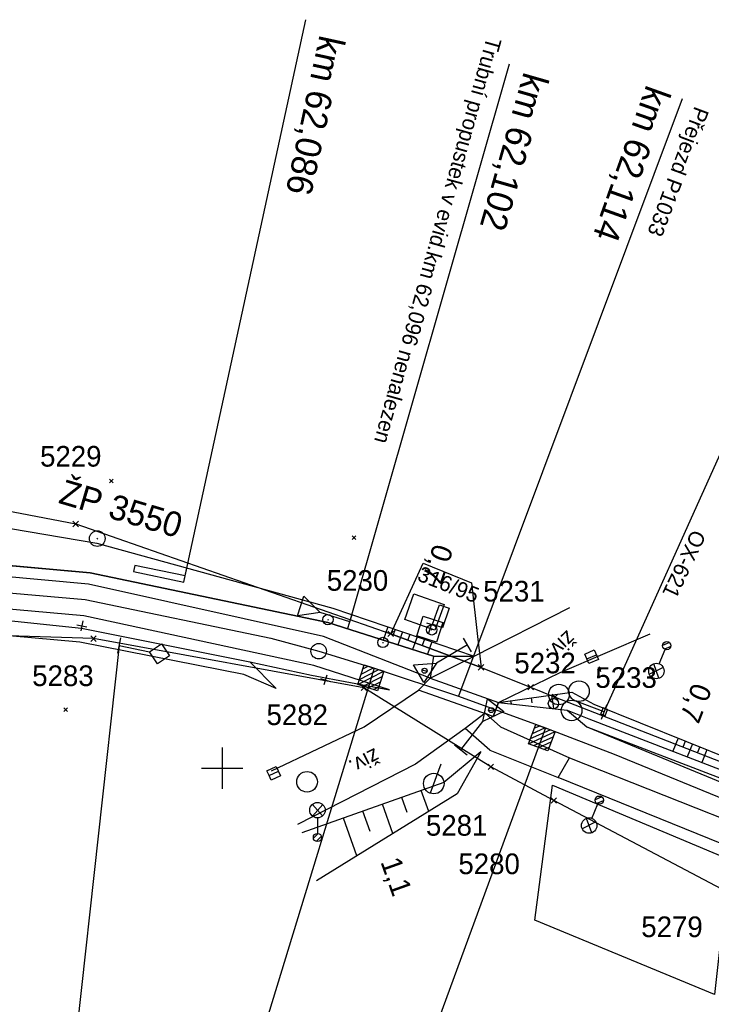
# Model space of a CAD drawing. Extents: x -805636 to -804553, y -1165340 to -1164656.
# Drawn here: x -805419.6 to -805352.6, y -1164922.9 to -1164827.5 of the extents above; entities that cross this region are included whole.
import ezdxf

# ---------------------------------------------------------------- set-up
doc = ezdxf.new("R2010")
doc.units = 0
for name, color, linetype in [('0381KM061-064P - Vrstva 1', 7, 'Continuous'), ('0381KM061-064P - Vrstva 12', 7, 'Continuous'), ('0381KM061-064P - Vrstva 16', 7, 'Continuous'), ('0381KM061-064P - Vrstva 17', 7, 'Continuous'), ('0381KM061-064P - Vrstva 19', 7, 'Continuous'), ('0381KM061-064P - Vrstva 23', 7, 'Continuous'), ('0381KM061-064P - Vrstva 25', 7, 'Continuous'), ('0381KM061-064P - Vrstva 27', 7, 'Continuous'), ('0381KM061-064P - Vrstva 3', 7, 'Continuous'), ('0381KM061-064P - Vrstva 33', 7, 'Continuous'), ('0381KM061-064P - Vrstva 4', 7, 'Continuous'), ('0381KM061-064P - Vrstva 43', 7, 'Continuous'), ('0381KM061-064P - Vrstva 48', 7, 'Continuous'), ('0381KM061-064P - Vrstva 49', 7, 'Continuous'), ('0381KM061-064P - Vrstva 51', 7, 'Continuous'), ('0381KM061-064P - Vrstva 55', 7, 'Continuous'), ('0381KM061-064P - Vrstva 57', 7, 'Continuous'), ('0381KM061-064P - Vrstva 7', 7, 'Continuous'), ('0381KM061-064P - Vrstva 8', 7, 'Continuous'), ('0381KM061-064P - Vrstva 9', 7, 'Continuous'), ('krizky_1000 - Vrstva 1', 7, 'Continuous'), ('szdc - hran DP', 7, 'Continuous'), ('szdc - szdc_cislo', 7, 'Continuous'), ('szdc - szdc_krizek', 7, 'Continuous'), ('vyt_sit - stávající', 7, 'Continuous')]:
    doc.layers.add(name, color=color, linetype=linetype)

msp = doc.modelspace()

# ---------------------------------------------------------------- linework, layer by layer
at = {"layer": '0381KM061-064P - Vrstva 1'}
msp.add_line((-805413.273, -1164883.656), (-805395.309, -1164887.389), dxfattribs=at)
for points in [[(-805621.704, -1164896.484), (-805615.585, -1164895.981), (-805590.014, -1164893.62), (-805528.478, -1164887.901), (-805486.763, -1164883.981), (-805461.299, -1164882.035), (-805437.692, -1164881.512), (-805413.273, -1164883.656)], [(-805395.309, -1164887.389), (-805390.659, -1164888.66), (-805385.303, -1164890.297), (-805377.115, -1164893.006), (-805368.704, -1164896.094), (-805362.065, -1164898.642)], [(-805362.065, -1164898.642), (-805347.387, -1164904.644), (-805344.651, -1164905.782)]]:
    msp.add_lwpolyline(points, dxfattribs=at)
at = {"layer": '0381KM061-064P - Vrstva 12'}
for p, q in [((-805363.346, -1164894.76), (-805363.111, -1164894.153)), ((-805362.921, -1164894.925), (-805362.686, -1164894.318)), ((-805362.921, -1164894.925), (-805362.686, -1164894.318))]:
    msp.add_line(p, q, dxfattribs=at)
for points in [[(-805363.346, -1164894.76), (-805363.346, -1164894.76), (-805363.111, -1164894.153), (-805363.111, -1164894.153), (-805362.686, -1164894.318), (-805362.686, -1164894.318), (-805363.111, -1164894.153)], [(-805363.346, -1164894.76), (-805362.921, -1164894.925), (-805362.921, -1164894.925), (-805363.346, -1164894.76)]]:
    msp.add_lwpolyline(points, dxfattribs=at)
at = {"layer": '0381KM061-064P - Vrstva 16'}
msp.add_lwpolyline([(-805366.38, -1164898.984), (-805348.12, -1164906.22), (-805348.611, -1164907.57), (-805349.086, -1164908.359), (-805367.461, -1164900.883), (-805366.38, -1164898.984)], dxfattribs=at)
at = {"layer": '0381KM061-064P - Vrstva 17'}
msp.add_lwpolyline([(-805369.748, -1164914.704), (-805368.039, -1164901.633), (-805350.89, -1164908.843), (-805352.324, -1164921.909), (-805369.748, -1164914.704)], dxfattribs=at)
at = {"layer": '0381KM061-064P - Vrstva 23'}
msp.add_lwpolyline([(-805382.318, -1164885.581), (-805381.437, -1164883.103), (-805378.521, -1164884.128), (-805379.402, -1164886.606)], close=True, dxfattribs=at)
at = {"layer": '0381KM061-064P - Vrstva 25'}
for p, q in [((-805356.707, -1164887.822), (-805357.359, -1164888.095)), ((-805356.572, -1164888.198), (-805357.183, -1164888.455)), ((-805357.681, -1164889.884), (-805357.113, -1164888.495)), ((-805357.305, -1164890.229), (-805358.64, -1164890.894)), ((-805357.719, -1164891.28), (-805358.218, -1164889.875)), ((-805391.275, -1164903.493), (-805390.281, -1164904.605)), ((-805391.26, -1164904.623), (-805390.276, -1164903.502)), ((-805364.199, -1164904.849), (-805363.647, -1164903.455)), ((-805363.248, -1164902.777), (-805363.897, -1164903.058)), ((-805363.108, -1164903.152), (-805363.717, -1164903.415)), ((-805390.781, -1164904.8), (-805390.781, -1164906.3)), ((-805363.819, -1164905.191), (-805365.147, -1164905.87)), ((-805364.221, -1164906.247), (-805364.735, -1164904.847)), ((-805391.17, -1164906.78), (-805390.701, -1164906.311)), ((-805390.902, -1164907.077), (-805390.402, -1164906.577))]:
    msp.add_line(p, q, dxfattribs=at)
msp.add_lwpolyline([(-805378.687, -1164886.382), (-805379.629, -1164886.047), (-805378.959, -1164884.162), (-805378.017, -1164884.497), (-805378.687, -1164886.382)], dxfattribs=at)
for centre, radius in [((-805356.962, -1164888.125), 0.4), ((-805356.962, -1164888.125), 0.4), ((-805357.962, -1164890.578), 0.749), ((-805363.499, -1164903.083), 0.4), ((-805363.499, -1164903.083), 0.4), ((-805390.784, -1164904.052), 0.749), ((-805364.472, -1164905.546), 0.749), ((-805390.781, -1164906.7), 0.4), ((-805390.781, -1164906.7), 0.4)]:
    msp.add_circle(centre, radius, dxfattribs=at)
at = {"layer": '0381KM061-064P - Vrstva 27'}
for p, q in [((-805379.668, -1164886.609), (-805379.762, -1164886.577)), ((-805384.49, -1164887.813), (-805384.39, -1164887.813)), ((-805367.983, -1164893.734), (-805367.883, -1164893.734))]:
    msp.add_line(p, q, dxfattribs=at)
for centre in [(-805379.715, -1164886.593), (-805384.44, -1164887.813), (-805367.933, -1164893.734)]:
    msp.add_circle(centre, 0.5, dxfattribs=at)
at = {"layer": '0381KM061-064P - Vrstva 3'}
for p, q in [((-805385.303, -1164890.297), (-805402.596, -1164946.877)), ((-805386.542, -1164890.886), (-805385.361, -1164890.278)), ((-805386.38, -1164890.381), (-805385.866, -1164890.116)), ((-805386.866, -1164891.896), (-805384.351, -1164890.603)), ((-805386.704, -1164891.391), (-805384.855, -1164890.441)), ((-805386.362, -1164892.058), (-805384.513, -1164891.107)), ((-805385.856, -1164892.22), (-805384.675, -1164891.613)), ((-805385.351, -1164892.382), (-805384.837, -1164892.117)), ((-805369.97, -1164896.623), (-805368.761, -1164896.073)), ((-805369.784, -1164896.126), (-805369.257, -1164895.887)), ((-805368.704, -1164896.094), (-805389.1, -1164951.648)), ((-805370.342, -1164897.616), (-805367.768, -1164896.445)), ((-805370.156, -1164897.12), (-805368.264, -1164896.259)), ((-805369.846, -1164897.802), (-805367.953, -1164896.941)), ((-805369.348, -1164897.988), (-805368.14, -1164897.438)), ((-805368.852, -1164898.174), (-805368.325, -1164897.935))]:
    msp.add_line(p, q, dxfattribs=at)
for points in [[(-805386.255, -1164889.991), (-805384.351, -1164890.603), (-805384.962, -1164892.507), (-805386.866, -1164891.896)], [(-805369.64, -1164895.743), (-805367.768, -1164896.445), (-805368.469, -1164898.318), (-805370.342, -1164897.616)]]:
    msp.add_lwpolyline(points, close=True, dxfattribs=at)
at = {"layer": '0381KM061-064P - Vrstva 33'}
for p, q in [((-805380.216, -1164885.895), (-805379.266, -1164886.209)), ((-805379.741, -1164886.052), (-805380.055, -1164887.002))]:
    msp.add_line(p, q, dxfattribs=at)
msp.add_lwpolyline([(-805380.533, -1164885.264), (-805378.635, -1164885.892), (-805379.263, -1164887.79), (-805381.161, -1164887.162), (-805380.533, -1164885.264)], dxfattribs=at)
at = {"layer": '0381KM061-064P - Vrstva 4'}
for p, q in [((-805355.471, -1164835.15), (-805377.115, -1164893.006)), ((-805437.823, -1164878.806), (-805412.781, -1164881.052)), ((-805412.96, -1164882.157), (-805437.678, -1164879.902)), ((-805412.781, -1164881.052), (-805389.788, -1164885.886)), ((-805390.184, -1164887.249), (-805412.96, -1164882.157)), ((-805379.867, -1164891.266), (-805390.184, -1164887.249)), ((-805375.866, -1164888.727), (-805376.654, -1164887.385)), ((-805380.174, -1164890.612), (-805380.647, -1164890.487)), ((-805374.205, -1164894.39), (-805373.719, -1164894.33)), ((-805377.504, -1164897.741), (-805376.274, -1164898.693))]:
    msp.add_line(p, q, dxfattribs=at)
for points in [[(-805383.815, -1164892.413), (-805391.138, -1164890.05), (-805413.398, -1164885.24), (-805437.693, -1164883.083), (-805461.239, -1164883.617), (-805489.811, -1164885.789), (-805528.465, -1164889.37), (-805589.939, -1164894.996), (-805615.477, -1164897.548), (-805622.384, -1164898.082)], [(-805622.831, -1164899.132), (-805615.585, -1164898.49), (-805589.92, -1164896.02), (-805528.493, -1164890.341), (-805490.028, -1164887.057), (-805461.175, -1164884.746), (-805437.909, -1164883.87), (-805413.614, -1164886.429), (-805397.335, -1164889.692), (-805391.357, -1164890.969), (-805383.815, -1164892.413)], [(-805389.788, -1164885.886), (-805379.556, -1164889.142), (-805379.867, -1164891.266)], [(-805376.26, -1164888.056), (-805379.252, -1164889.828), (-805380.475, -1164891.699), (-805381.498, -1164889.982), (-805379.252, -1164889.828)], [(-805380.989, -1164892.419), (-805379.867, -1164891.266), (-805373.247, -1164893.625), (-805373.771, -1164894.981), (-805380.989, -1164892.419)], [(-805376.889, -1164898.217), (-805374.77, -1164895.461), (-805374.329, -1164893.269), (-805372.742, -1164894.482), (-805374.77, -1164895.461)], [(-805364.7, -1164895.967), (-805343.186, -1164904.858), (-805317.028, -1164915.677), (-805296.749, -1164924.424), (-805284.829, -1164929.565), (-805254.696, -1164942.255), (-805226.161, -1164954.547), (-805203.522, -1164964.184), (-805187.57, -1164970.915)], [(-805364.7, -1164895.967), (-805342.905, -1164904.361), (-805316.813, -1164915.122), (-805296.457, -1164924.126), (-805284.518, -1164929.127), (-805254.445, -1164941.834), (-805225.915, -1164953.926), (-805203.376, -1164963.468), (-805187.403, -1164970.449)]]:
    msp.add_lwpolyline(points, dxfattribs=at)
for centre in [(-805380.409, -1164890.548), (-805373.963, -1164894.361)]:
    msp.add_circle(centre, 0.248, dxfattribs=at)
at = {"layer": '0381KM061-064P - Vrstva 43'}
msp.add_line((-805378.821, -1164899.606), (-805379.871, -1164902.412), dxfattribs=at)
for points in [[(-805364.696, -1164889.394), (-805364.894, -1164888.935), (-805363.975, -1164888.54), (-805363.58, -1164889.459), (-805364.499, -1164889.854), (-805364.696, -1164889.394), (-805363.778, -1164889)], [(-805395.465, -1164900.701), (-805395.679, -1164900.249), (-805394.776, -1164899.82), (-805394.347, -1164900.723), (-805395.25, -1164901.152), (-805395.465, -1164900.701), (-805394.561, -1164900.271)]]:
    msp.add_lwpolyline(points, dxfattribs=at)
for centre, radius in [((-805391.787, -1164901.307), 1), ((-805379.522, -1164901.479), 0.996)]:
    msp.add_circle(centre, radius, dxfattribs=at)
at = {"layer": '0381KM061-064P - Vrstva 48'}
for p, q in [((-805383.98, -1164886.283), (-805384.426, -1164887.592)), ((-805383.27, -1164886.525), (-805383.491, -1164887.172)), ((-805382.56, -1164886.767), (-805382.996, -1164888.047)), ((-805381.85, -1164887.008), (-805382.066, -1164887.642)), ((-805381.14, -1164887.25), (-805381.567, -1164888.502)), ((-805380.43, -1164887.492), (-805380.641, -1164888.111)), ((-805379.72, -1164887.734), (-805380.137, -1164888.957)), ((-805370.004, -1164893.663), (-805370.072, -1164893.177)), ((-805367.91, -1164894.212), (-805368.096, -1164892.898)), ((-805372.006, -1164893.762), (-805372.049, -1164893.457)), ((-805355.86, -1164897.081), (-805356.367, -1164898.342)), ((-805355.164, -1164897.361), (-805355.416, -1164897.987)), ((-805354.468, -1164897.641), (-805354.968, -1164898.883)), ((-805353.772, -1164897.921), (-805354.02, -1164898.537)), ((-805353.077, -1164898.201), (-805353.569, -1164899.425)), ((-805380.012, -1164904.18), (-805380.735, -1164902.147)), ((-805383.487, -1164906.33), (-805384.499, -1164903.486)), ((-805382.096, -1164904.28), (-805382.617, -1164902.817)), ((-805385.688, -1164906.105), (-805386.381, -1164904.156)), ((-805386.963, -1164908.479), (-805388.263, -1164904.826))]:
    msp.add_line(p, q, dxfattribs=at)
at = {"layer": '0381KM061-064P - Vrstva 49'}
for p, q in [((-805410.559, -1164872.335), (-805410.913, -1164871.981)), ((-805410.559, -1164871.981), (-805410.913, -1164872.335)), ((-805387.058, -1164877.826), (-805387.412, -1164877.472)), ((-805387.058, -1164877.472), (-805387.412, -1164877.826)), ((-805363.681, -1164890.452), (-805363.195, -1164890.338)), ((-805363.495, -1164890.152), (-805363.381, -1164890.638)), ((-805366.166, -1164892.624), (-805364.02, -1164893.798)), ((-805414.987, -1164894.494), (-805415.341, -1164894.14)), ((-805414.987, -1164894.14), (-805415.341, -1164894.494)), ((-805366.61, -1164894.354), (-805364.491, -1164895.197))]:
    msp.add_line(p, q, dxfattribs=at)
for points in [[(-805619.348, -1164890.946), (-805615.907, -1164890.53), (-805590.563, -1164886.386), (-805529.034, -1164882.212), (-805489.902, -1164877.68), (-805461.977, -1164874.39), (-805438.957, -1164873.655), (-805412.144, -1164878.198), (-805389.289, -1164884.476), (-805375.598, -1164889.137)], [(-805379.556, -1164889.142), (-805389.788, -1164885.886), (-805412.781, -1164881.052), (-805437.823, -1164878.806), (-805461.56, -1164879.343), (-805490.633, -1164881.901), (-805528.628, -1164885.468), (-805589.685, -1164890.913), (-805616.183, -1164893.177), (-805620.48, -1164893.608)], [(-805622.831, -1164899.132), (-805615.585, -1164898.49), (-805589.92, -1164896.02), (-805528.493, -1164890.341), (-805490.028, -1164887.057), (-805461.175, -1164884.746), (-805437.909, -1164883.87), (-805413.614, -1164886.429), (-805397.335, -1164889.692), (-805394.785, -1164892.277)], [(-805394.785, -1164892.277), (-805397.926, -1164890.9), (-805413.803, -1164887.771), (-805437.965, -1164885.619), (-805460.375, -1164886.37), (-805489.928, -1164888.57), (-805513.347, -1164890.238), (-805537.397, -1164892.439), (-805590.643, -1164897.221), (-805615.625, -1164899.613), (-805623.383, -1164900.43)], [(-805379.556, -1164889.142), (-805375.598, -1164889.137)], [(-805373.247, -1164893.625), (-805366.166, -1164892.624)], [(-805373.247, -1164893.625), (-805366.61, -1164894.354)], [(-805364.02, -1164893.798), (-805346.07, -1164901.02), (-805315.869, -1164912.655), (-805295.191, -1164922.013)], [(-805366.61, -1164894.354), (-805364.7, -1164895.967), (-805342.905, -1164904.361), (-805316.813, -1164915.122), (-805296.457, -1164924.126)], [(-805364.491, -1164895.197), (-805347.099, -1164901.929), (-805316.44, -1164914.009), (-805295.936, -1164922.853)], [(-805374.968, -1164898.413), (-805378.547, -1164901.368), (-805392.285, -1164906.256)], [(-805374.968, -1164898.413), (-805377.244, -1164902.467), (-805390.884, -1164910.902)]]:
    msp.add_lwpolyline(points, dxfattribs=at)
at = {"layer": '0381KM061-064P - Vrstva 51'}
for p, q in [((-805380.989, -1164892.419), (-805379.867, -1164891.266)), ((-805373.064, -1164895.987), (-805366.38, -1164898.984)), ((-805374.087, -1164898.252), (-805367.461, -1164900.883))]:
    msp.add_line(p, q, dxfattribs=at)
for points in [[(-805379.867, -1164891.266), (-805375.598, -1164889.137), (-805366.336, -1164884.418)], [(-805373.247, -1164893.625), (-805367.287, -1164890.728), (-805358.552, -1164886.973)], [(-805395.217, -1164900.25), (-805386.262, -1164895.996), (-805380.989, -1164892.419)], [(-805374.558, -1164894.674), (-805373.771, -1164894.981), (-805373.247, -1164893.625)], [(-805374.558, -1164894.674), (-805376.473, -1164896.142), (-805381.294, -1164899.603), (-805392.724, -1164905.437)], [(-805373.064, -1164895.987), (-805374.558, -1164894.674)], [(-805374.087, -1164898.252), (-805376.473, -1164896.142)]]:
    msp.add_lwpolyline(points, dxfattribs=at)
at = {"layer": '0381KM061-064P - Vrstva 55'}
msp.add_lwpolyline([(-805383.69, -1164886.97), (-805380.55, -1164880.12), (-805375.86, -1164882.04), (-805375.28, -1164887.22), (-805374.94, -1164890.22)], close=True, dxfattribs=at)
at = {"layer": '0381KM061-064P - Vrstva 7'}
for p, q in [((-805389.817, -1164885.586), (-805389.723, -1164885.618)), ((-805414.092, -1164886.107), (-805413.112, -1164886.311)), ((-805413.5, -1164885.719), (-805413.704, -1164886.699)), ((-805390.497, -1164891.304), (-805389.541, -1164891.596)), ((-805389.873, -1164890.972), (-805390.165, -1164891.928))]:
    msp.add_line(p, q, dxfattribs=at)
for centre, radius in [((-805389.77, -1164885.602), 0.5), ((-805390.659, -1164888.66), 0.75)]:
    msp.add_circle(centre, radius, dxfattribs=at)
at = {"layer": '0381KM061-064P - Vrstva 8'}
for p, q in [((-805387.651, -1164885.818), (-805372.19, -1164831.771)), ((-805363.016, -1164894.539), (-805338.796, -1164840.623)), ((-805392.106, -1164883.338), (-805390.508, -1164884.901)), ((-805387.88, -1164886.532), (-805387.422, -1164885.104)), ((-805409.843, -1164887.368), (-805410.149, -1164888.836)), ((-805409.996, -1164888.102), (-805416.328, -1164945.947)), ((-805363.016, -1164894.539), (-805365.817, -1164893.464)), ((-805363.285, -1164895.239), (-805362.747, -1164893.839))]:
    msp.add_line(p, q, dxfattribs=at)
for points in [[(-805387.651, -1164885.818), (-805390.508, -1164884.901), (-805392.717, -1164885.243), (-805392.106, -1164883.338), (-805390.508, -1164884.901)], [(-805409.996, -1164888.102), (-805407.059, -1164888.712), (-805405.876, -1164887.937), (-805405.101, -1164889.119), (-805406.283, -1164889.895), (-805407.059, -1164888.712)]]:
    msp.add_lwpolyline(points, dxfattribs=at)
for centre in [(-805367.404, -1164892.855), (-805365.458, -1164892.53), (-805366.175, -1164894.398)]:
    msp.add_circle(centre, 1, dxfattribs=at)
at = {"layer": '0381KM061-064P - Vrstva 9'}
for p, q in [((-805403.645, -1164881.663), (-805391.903, -1164827.491)), ((-805408.479, -1164880.352), (-805408.601, -1164880.939)), ((-805403.584, -1164881.369), (-805408.479, -1164880.352)), ((-805403.584, -1164881.369), (-805403.462, -1164880.782)), ((-805408.601, -1164880.939), (-805403.706, -1164881.957)), ((-805403.706, -1164881.957), (-805403.584, -1164881.369))]:
    msp.add_line(p, q, dxfattribs=at)
at = {"layer": 'krizky_1000 - Vrstva 1'}
for points in [[(-805400, -1164898), (-805400, -1164902)], [(-805402, -1164900), (-805398, -1164900)]]:
    msp.add_lwpolyline(points, dxfattribs=at)
at = {"layer": 'szdc - hran DP'}
for p, q in [((-805433.01, -1164872.7), (-805414.192, -1164876.333)), ((-805414.192, -1164876.333), (-805383.69, -1164886.97)), ((-805412.47, -1164887.438), (-805443.504, -1164886.48)), ((-805386.3, -1164892.2), (-805412.47, -1164887.438)), ((-805383.69, -1164886.97), (-805374.94, -1164890.22)), ((-805374.94, -1164890.22), (-805370.14, -1164892.15)), ((-805373.995, -1164899.863), (-805386.3, -1164892.2)), ((-805370.14, -1164892.15), (-805367.78, -1164893.1)), ((-805367.78, -1164893.1), (-805249.75, -1164939.24)), ((-805367.9, -1164903.11), (-805373.995, -1164899.863)), ((-805346.65, -1164914.36), (-805367.9, -1164903.11))]:
    msp.add_line(p, q, dxfattribs=at)
at = {"layer": 'szdc - szdc_krizek'}
for p, q in [((-805413.927, -1164876.598), (-805414.458, -1164876.068)), ((-805414.458, -1164876.598), (-805413.927, -1164876.068)), ((-805412.205, -1164887.703), (-805412.736, -1164887.173)), ((-805412.736, -1164887.703), (-805412.205, -1164887.173)), ((-805383.425, -1164887.235), (-805383.956, -1164886.705)), ((-805383.956, -1164887.235), (-805383.425, -1164886.705)), ((-805374.675, -1164890.485), (-805375.206, -1164889.955)), ((-805375.206, -1164890.485), (-805374.675, -1164889.955)), ((-805386.035, -1164892.465), (-805386.566, -1164891.935)), ((-805386.566, -1164892.465), (-805386.035, -1164891.935)), ((-805369.875, -1164892.415), (-805370.406, -1164891.885)), ((-805370.406, -1164892.415), (-805369.875, -1164891.885)), ((-805367.515, -1164893.365), (-805368.046, -1164892.835)), ((-805368.046, -1164893.365), (-805367.515, -1164892.835)), ((-805373.73, -1164900.128), (-805374.261, -1164899.598)), ((-805374.261, -1164900.128), (-805373.73, -1164899.598)), ((-805367.635, -1164903.375), (-805368.166, -1164902.845)), ((-805368.166, -1164903.375), (-805367.635, -1164902.845))]:
    msp.add_line(p, q, dxfattribs=at)
at = {"layer": 'vyt_sit - stávající'}
msp.add_line((-805412.142, -1164877.72), (-805412.056, -1164877.772), dxfattribs=at)
msp.add_circle((-805412.099, -1164877.746), 0.756, dxfattribs=at)

# ---------------------------------------------------------------- texts
at = {"layer": '0381KM061-064P - Vrstva 19'}
msp.add_text('Trubní propustek v evid.km 62,096 nenalezen', height=1.5, rotation=254.42079, dxfattribs=at).set_placement((-805374.385, -1164829.091))
at = {"layer": '0381KM061-064P - Vrstva 4'}
for s, height, rotation, p in [('km 62,114', 2.5, 250.38676, (-805358.906, -1164833.705)), ('Přejezd P1033', 1.5, 249.48912, (-805354.244, -1164835.801))]:
    msp.add_text(s, height=height, rotation=rotation, dxfattribs=at).set_placement(p)
at = {"layer": '0381KM061-064P - Vrstva 48'}
for s, rotation, p in [('0,7', 251.19924, (-805379.492, -1164878.141)), ('0,7', 248.83985, (-805354.411, -1164891.596)), ('1,1', 289.58563, (-805384.703, -1164909.05))]:
    msp.add_text(s, height=2, rotation=rotation, dxfattribs=at).set_placement(p)
at = {"layer": '0381KM061-064P - Vrstva 51'}
for rotation, p in [(223.26189, (-805366.606, -1164886.554)), (207.04028, (-805385.241, -1164897.992))]:
    msp.add_text('živ.', height=1.5, rotation=rotation, dxfattribs=at).set_placement(p)
at = {"layer": '0381KM061-064P - Vrstva 57'}
msp.add_text('316/95', height=1.5, rotation=338.44566, dxfattribs=at).set_placement((-805381.221, -1164881.768))
at = {"layer": '0381KM061-064P - Vrstva 8'}
for s, height, rotation, p in [('km 62,102', 2.5, 254.03601, (-805370.785, -1164832.462)), ('OX-621', 1.5, 244.71513, (-805354.469, -1164876.784))]:
    msp.add_text(s, height=height, rotation=rotation, dxfattribs=at).set_placement(p)
at = {"layer": '0381KM061-064P - Vrstva 9'}
msp.add_text('km 62,086', height=2.5, rotation=257.7697, dxfattribs=at).set_placement((-805390.557, -1164828.887))
at = {"layer": 'szdc - szdc_cislo'}
for s, p in [('5229', (-805417.64, -1164870.778)), ('5230', (-805389.877, -1164882.803)), ('5231', (-805374.734, -1164883.844)), ('5232', (-805371.719, -1164890.797)), ('5283', (-805418.404, -1164892.035)), ('5233', (-805363.873, -1164892.209)), ('5282', (-805395.717, -1164895.814)), ('5281', (-805380.279, -1164906.527)), ('5280', (-805377.135, -1164910.25)), ('5279', (-805359.424, -1164916.35))]:
    msp.add_text(s, height=2, dxfattribs=at).set_placement(p)
at = {"layer": 'vyt_sit - stávající'}
msp.add_text('ŽP 3550', height=2.4, rotation=343.5611, dxfattribs=at).set_placement((-805415.959, -1164874.278))

doc.saveas('drawing.dxf')
